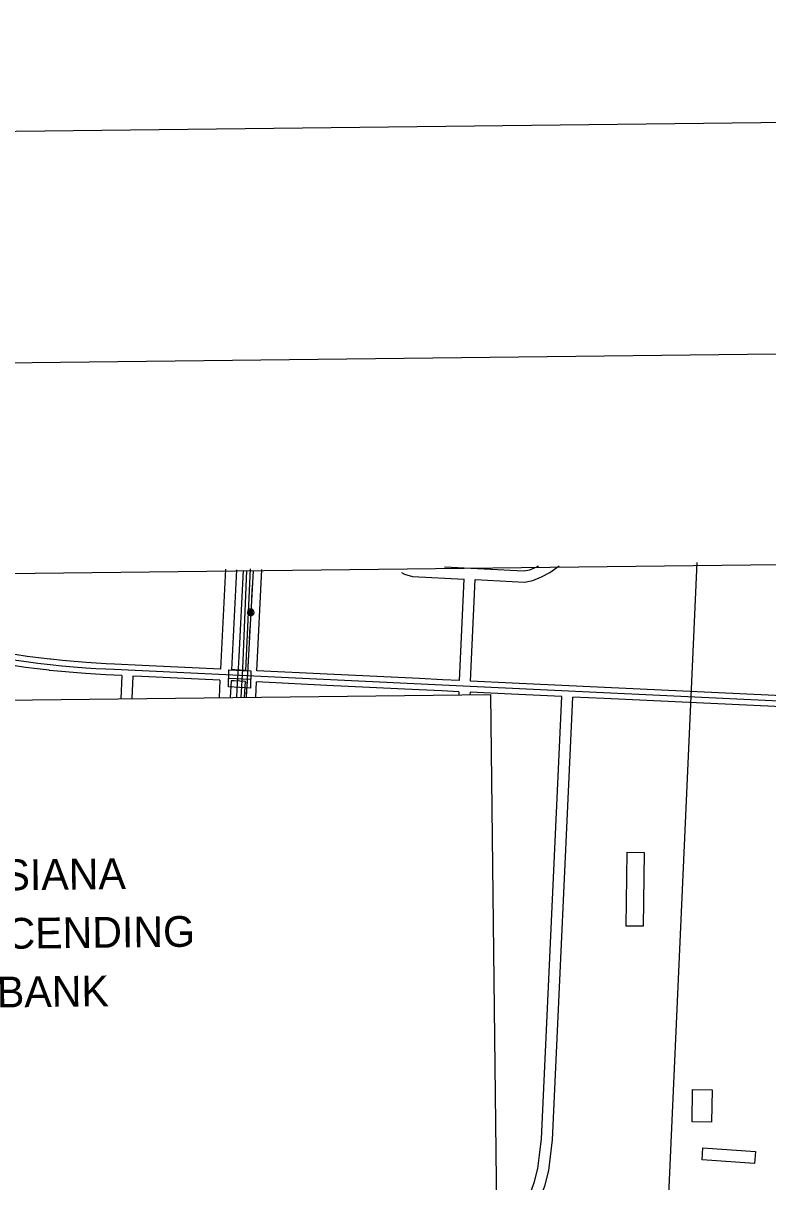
# Model space of a CAD drawing. Extents: x 3683402 to 3721514, y 487807 to 513565.
# Drawn here: x 3695530 to 3697541, y 509855 to 512982 of the extents above; entities that cross this region are included whole.
import ezdxf

# ---------------------------------------------------------------- set-up
doc = ezdxf.new("R2010")
doc.units = 0
for name, color, linetype in [('G-ANNO-NPLT', 7, 'Continuous'), ('V-ANNO-SYMB', 7, 'Continuous'), ('V-BLDG-OTLN', 7, 'Continuous'), ('V-BRDG-OTLN', 7, 'Continuous'), ('V-GRID-FRAM', 7, 'Continuous'), ('V-ROAD-CNTR', 7, 'Continuous'), ('V-TOPO-SHOR', 7, 'Continuous'), ('V-UTIL-LINE', 7, 'Continuous')]:
    doc.layers.add(name, color=color, linetype=linetype)

msp = doc.modelspace()

# ---------------------------------------------------------------- linework, layer by layer
at = {"layer": 'G-ANNO-NPLT'}
msp.add_lwpolyline([(3684266.3, 488390.6), (3720930.5, 488816.8), (3720649.6, 512981.8), (3683985.4, 512555.6)], close=True, dxfattribs=at)
at = {"layer": 'V-ANNO-SYMB'}
msp.add_lwpolyline([(3687009, 489047.6), (3720089.9, 489432.1), (3719823.5, 512347.2), (3686742.6, 511962.6), (3687009, 489047.6)], dxfattribs=at)
msp.add_lwpolyline([(3687900.3, 511066.8), (3696792.8, 511170.1), (3696858.2, 505541.9), (3687965.7, 505438.5)], close=True, dxfattribs=at)
at = {"layer": 'V-BLDG-OTLN'}
for points in [[(3697159.1, 510545.1), (3697161.6, 510744.2), (3697207.4, 510743.7), (3697204.9, 510544.6)], [(3697389.7, 510015.9), (3697337.3, 510016.6), (3697338.4, 510104.1), (3697390.8, 510103.4)], [(3697366.3, 509946.4), (3697507.8, 509937.1), (3697505.6, 509904.6), (3697364.2, 509913.9)]]:
    msp.add_lwpolyline(points, close=True, dxfattribs=at)
at = {"layer": 'V-BRDG-OTLN'}
msp.add_line((3696085.6, 511214.1), (3696144.7, 511211.3), dxfattribs=at)
msp.add_lwpolyline([(3696086.1, 511236.8), (3696145.3, 511233.9), (3696144.1, 511187.3), (3696085.1, 511190.8)], close=True, dxfattribs=at)
at = {"layer": 'V-GRID-FRAM'}
msp.add_lwpolyline([(3687448, 511403.5), (3719130.8, 511772.1), (3719350.3, 493590.7), (3687651.7, 493221.8), (3687448, 511403.5)], dxfattribs=at)
at = {"layer": 'V-ROAD-CNTR'}
for points in [[(3696668.3, 511514.3), (3696882.1, 511503.5), (3696898.3, 511506.7), (3696917.2, 511514.6), (3696921.9, 511517)], [(3696751, 511480.1), (3696884.3, 511473.3), (3696907.1, 511477.9), (3696929.8, 511487.4), (3696953, 511499.1), (3696978.2, 511517.7)], [(3697090.6, 505722.8), (3697350.6, 511526.5)], [(3696076.5, 511508.1), (3696063.5, 511238.5)], [(3696106.5, 511506.6), (3696093.5, 511237)], [(3696132, 511235.2), (3696144.7, 511508.8)], [(3696161.9, 511233.8), (3696174.7, 511507.5)], [(3696552.1, 511499.6), (3696560.4, 511495.1), (3696582, 511488.6), (3696721, 511481.6)], [(3696708.7, 511207.7), (3696721, 511481.6)], [(3696738.7, 511206.3), (3696751, 511480.1)], [(3695603.7, 511265.2), (3695571.9, 511268.9), (3695540.9, 511272.9), (3695507.8, 511277.7), (3695474.8, 511282.9), (3695445.5, 511287.9), (3695418.4, 511292.9), (3695390.7, 511298.3), (3695358.4, 511305)], [(3695600.3, 511235.4), (3695568.2, 511239.1), (3695536.8, 511243.2), (3695503.3, 511248), (3695469.9, 511253.3), (3695440.3, 511258.4), (3695412.8, 511263.4), (3695384.8, 511268.9), (3695352.3, 511275.7)], [(3698348.6, 511115.2), (3696661.9, 511194.9), (3695776.2, 511237.2), (3695754, 511238.2), (3695726.4, 511239.7), (3695699.5, 511241.4), (3695666.7, 511243.9), (3695635.3, 511246.8), (3695603.6, 511250.1), (3695570.1, 511254), (3695538.9, 511258.1), (3695505.6, 511262.9)], [(3695852.1, 511248.6), (3695776.9, 511252.2), (3695754.8, 511253.1), (3695727.3, 511254.6), (3695700.6, 511256.4), (3695668, 511258.9), (3695636.7, 511261.7), (3695605.2, 511265), (3695603.7, 511265.2)], [(3695796.8, 511221.2), (3695775.6, 511222.2), (3695753.3, 511223.2), (3695725.5, 511224.7), (3695698.5, 511226.4), (3695665.5, 511229), (3695633.8, 511231.9), (3695601.9, 511235.2), (3695600.3, 511235.4)], [(3696063.5, 511238.5), (3695852.1, 511248.6)], [(3696101.8, 511236.6), (3696093.5, 511237)], [(3696132, 511235.2), (3696101.8, 511236.6)], [(3696351.5, 511224.7), (3696161.9, 511233.8)], [(3695796.8, 511221.2), (3695793.8, 511158.5)], [(3695826.8, 511219.8), (3695823.9, 511158.9)], [(3695850.7, 511218.6), (3695826.8, 511219.8)], [(3696062, 511208.5), (3695850.7, 511218.6)], [(3696062, 511208.5), (3696059.8, 511161.6)], [(3696092, 511207.1), (3696089.8, 511162)], [(3696100.4, 511206.7), (3696092, 511207.1)], [(3696130.6, 511205.2), (3696100.4, 511206.7)], [(3696128.6, 511162.4), (3696130.6, 511205.2)], [(3696158.6, 511162.8), (3696160.5, 511203.8)], [(3696350.1, 511194.7), (3696160.5, 511203.8)], [(3696601.2, 511212.8), (3696351.5, 511224.7)], [(3696708.7, 511207.7), (3696662.6, 511209.8), (3696601.2, 511212.8)], [(3696851, 511200.9), (3696738.7, 511206.3)], [(3697100.7, 511189.1), (3696851, 511200.9)], [(3696599.8, 511182.8), (3696350.1, 511194.7)], [(3696707.3, 511177.7), (3696661.2, 511179.9), (3696599.8, 511182.8)], [(3696707.3, 511177.7), (3696706.9, 511169.1)], [(3696737.3, 511176.3), (3696737, 511169.5)], [(3696849.5, 511171), (3696737.3, 511176.3)], [(3696985.2, 511164.6), (3696849.5, 511171)], [(3697350.4, 511177.4), (3697100.7, 511189.1)], [(3697600.1, 511165.6), (3697350.4, 511177.4)], [(3696810.5, 509645.4), (3696855.7, 509730.9), (3696871.3, 509762.5), (3696886.3, 509794.7), (3696902.5, 509829.9), (3696911.6, 509855.8), (3696920.4, 509890.8), (3696924.9, 509927.2), (3696930, 509970.7), (3696985.2, 511164.6)], [(3696811.3, 509582.6), (3696882.4, 509717.2), (3696898.4, 509749.5), (3696913.5, 509782.1), (3696930.3, 509818.6), (3696940.4, 509847.2), (3696949.9, 509885.3), (3696954.7, 509923.6), (3696959.9, 509968.2), (3697015.2, 511163.2)], [(3697099.3, 511159.2), (3697015.2, 511163.2)], [(3697349, 511147.4), (3697099.3, 511159.2)], [(3697598.7, 511135.6), (3697349, 511147.4)]]:
    msp.add_lwpolyline(points, dxfattribs=at)
at = {"layer": 'V-TOPO-SHOR'}
for points in [[(3696107.5, 511162.2), (3696108.6, 511185.1), (3696112, 511240), (3696113.7, 511272.3), (3696125.4, 511504.4)], [(3696133.9, 511504.5), (3696122.7, 511239.6), (3696118.5, 511162.3)]]:
    msp.add_lwpolyline(points, dxfattribs=at)
at = {"layer": 'V-UTIL-LINE'}
for points in [[(3696151.2, 511504.7), (3696132.6, 511162.5)], [(3696151.2, 511504.7), (3696151.2, 511504.7)], [(3696149, 511464.8), (3696147.2, 511430.8)], [(3696145.1, 511391.9), (3696147.5, 511393.4), (3696145.4, 511394.3), (3696143.1, 511392.8), (3696143.3, 511389.9), (3696146.6, 511389.6), (3696150.2, 511392.6), (3696148.6, 511396.6), (3696144, 511398.1), (3696140.5, 511395.2), (3696139.3, 511390.9), (3696142.1, 511387.1), (3696147.6, 511386.4), (3696154.1, 511391.4), (3696153.6, 511394.9), (3696151.8, 511397.9), (3696149, 511400), (3696145.6, 511400.9), (3696142.1, 511400.4), (3696139.1, 511398.6), (3696137, 511395.8), (3696136.1, 511392.4), (3696136.6, 511388.9), (3696138.4, 511385.9), (3696141.2, 511383.8), (3696144.6, 511382.9), (3696148.1, 511383.4), (3696151.1, 511385.2), (3696153.2, 511388), (3696154.1, 511391.4)], [(3696143, 511353), (3696141.1, 511319)], [(3696139, 511279.1), (3696137.1, 511245.1)], [(3696135, 511205.2), (3696133.1, 511171.2)]]:
    msp.add_lwpolyline(points, dxfattribs=at)

# ---------------------------------------------------------------- texts
at = {"layer": 'V-ANNO-SYMB'}
for s, p in [('LOUISIANA ', (3695216, 510638.5)), ('RIGHT DESCENDING ', (3694878.9, 510476.6)), ('BANK', (3695460, 510325.3))]:
    msp.add_text(s, height=83, rotation=0.666, dxfattribs=at).set_placement(p)

doc.saveas('drawing.dxf')
